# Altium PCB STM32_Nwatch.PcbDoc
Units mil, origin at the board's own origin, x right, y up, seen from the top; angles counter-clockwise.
Board outline 1470.25 x 1330 mil, 2 copper layers (Top Layer, Bottom Layer); 62 components, 59 nets, 208 pads, 89 vias.
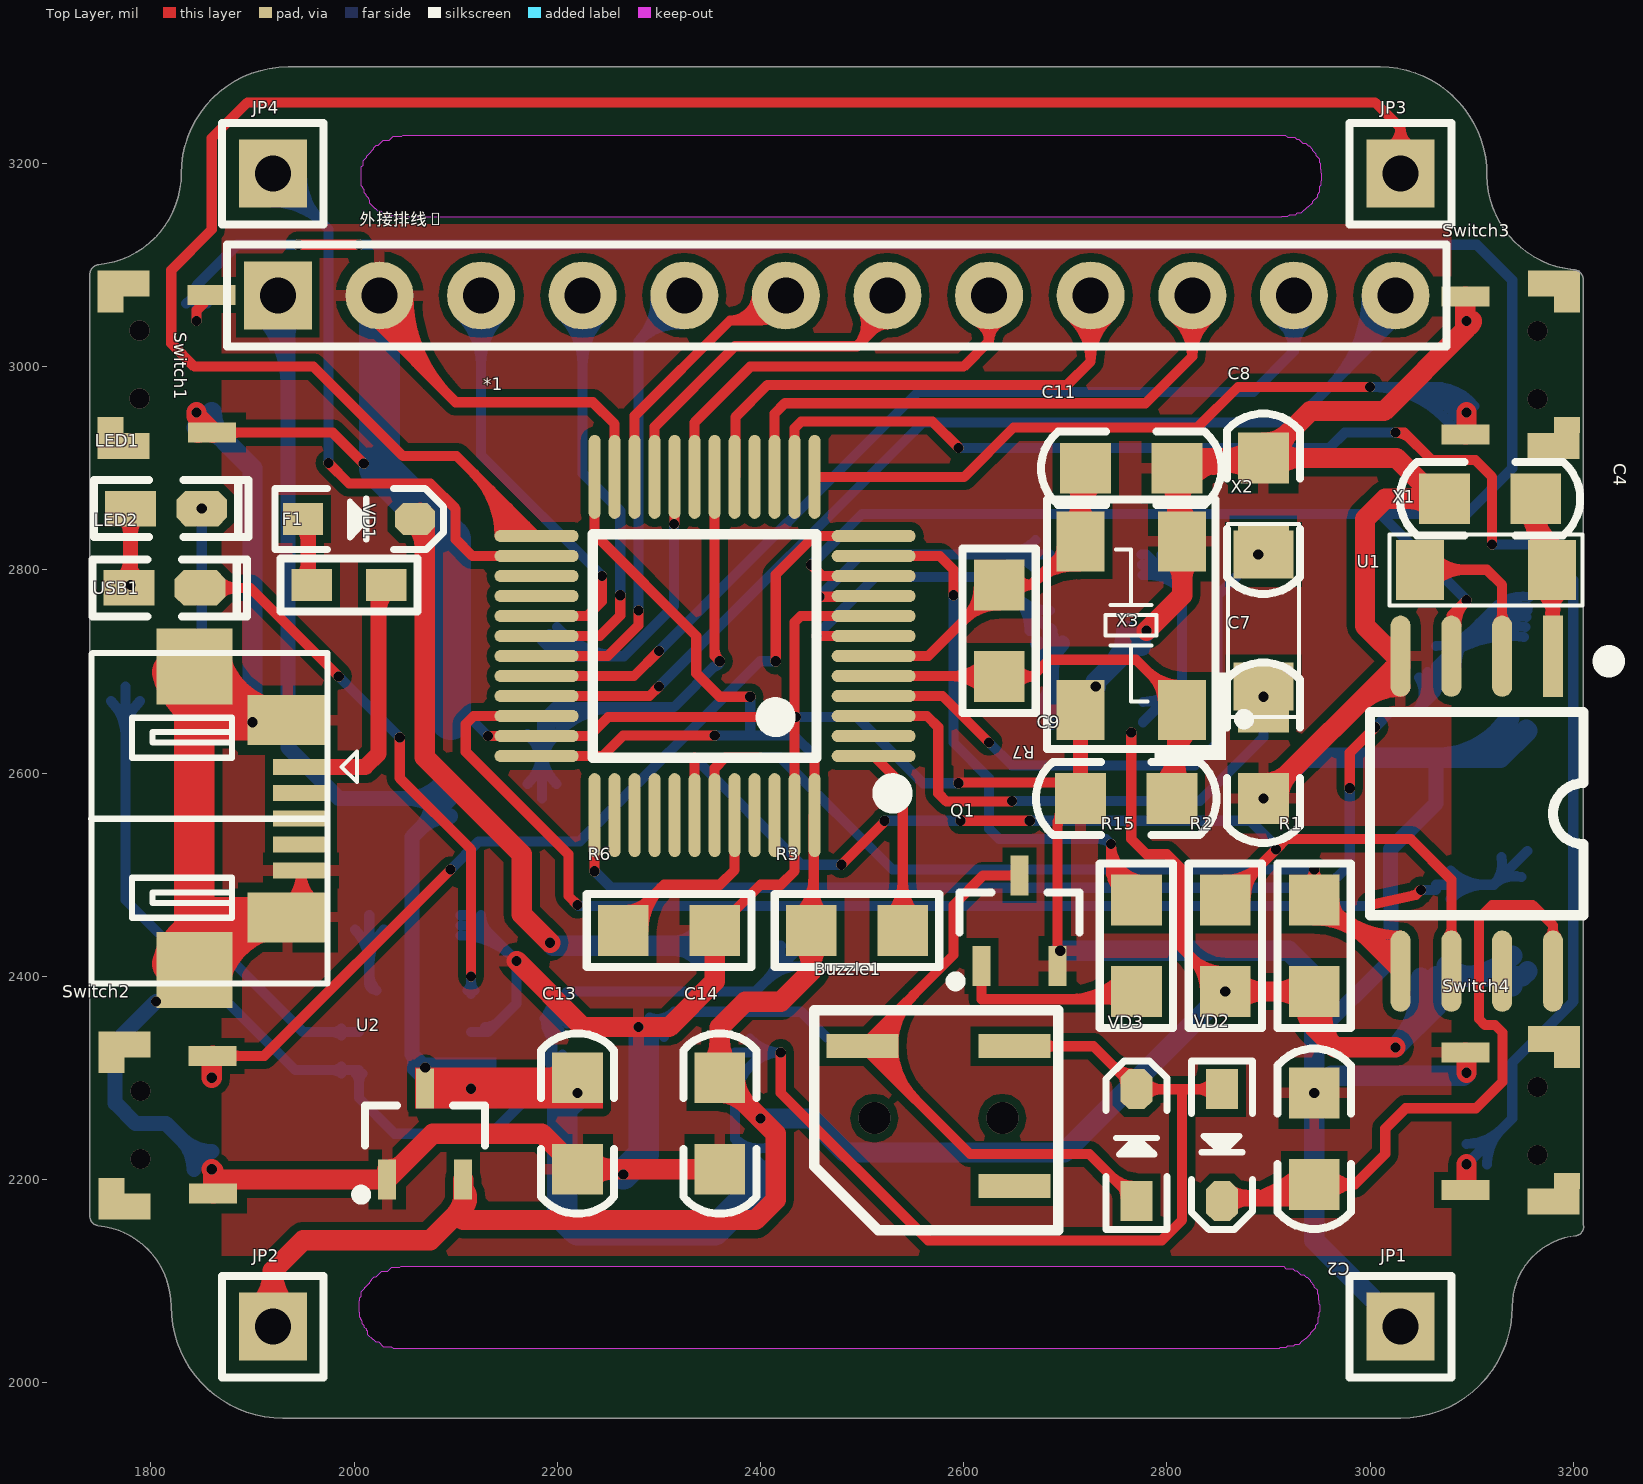
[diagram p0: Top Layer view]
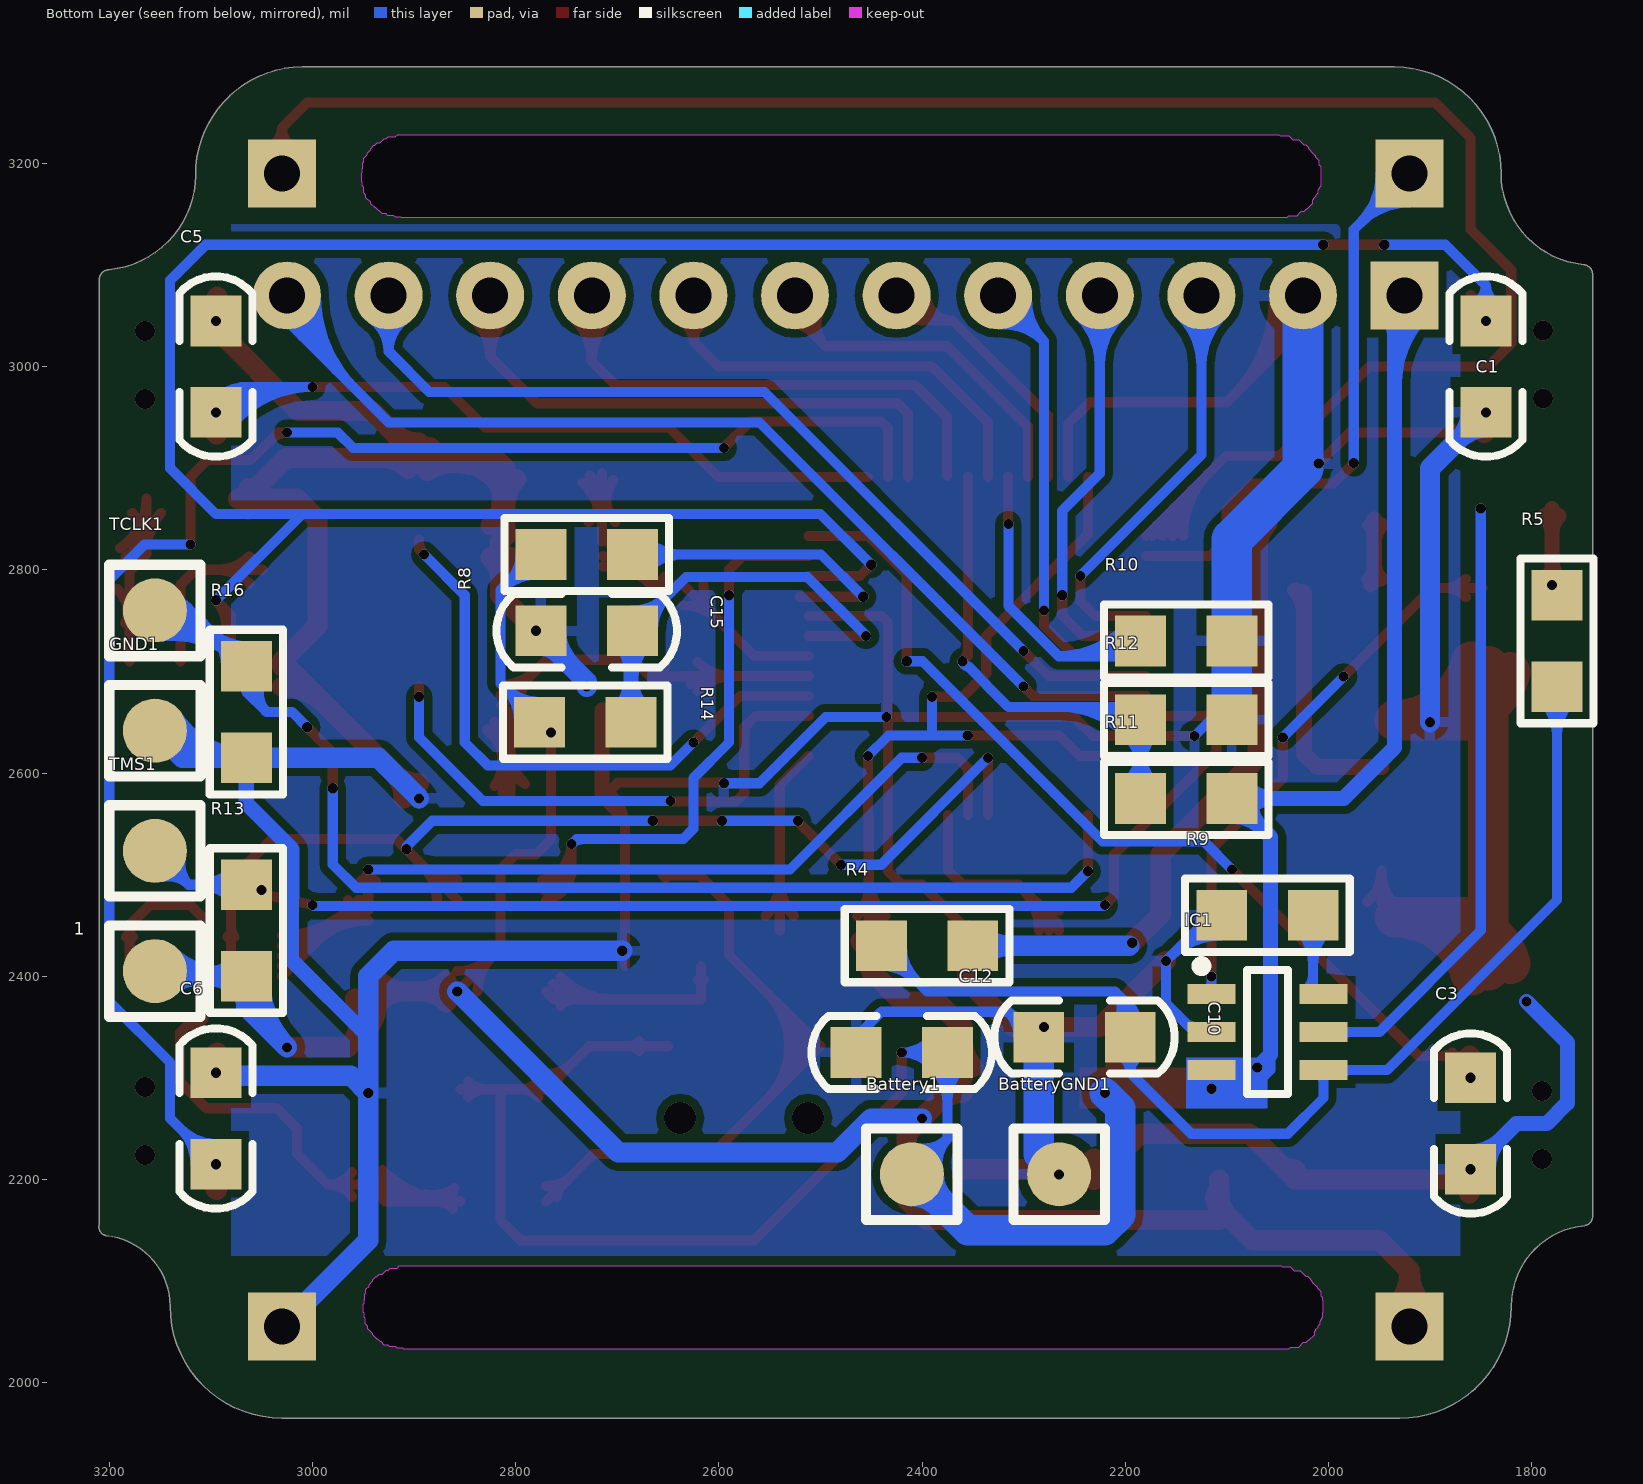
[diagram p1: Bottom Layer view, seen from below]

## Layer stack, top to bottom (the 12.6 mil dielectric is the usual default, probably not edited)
Top Solder: solder mask 0.4, Solder Resist, Dk 3.5
Top Layer: signal copper 1.4
Dielectric 1: dielectric 12.6, FR-4, Dk 4.8
Bottom Layer: signal copper 1.4
Bottom Solder: solder mask 0.4, Solder Resist, Dk 3.5

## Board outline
1820,2075 ccw(c1740,2075) 1747.84,2154.61 cw(c1749.11,2163.73) 1740,2165 1740,3090 cw(c1749.63,3090.81) 1748.82,3100.43 ccw(c1740,3190) 1830,3190 cw(c1935,3190) 1935,3295 3010,3295 cw(c3009.17,3189.17) 3115,3188.35 ccw(c3209.17,3189.17) 3199.94,3095.45 cw(c3199.75,3085.2) 3210,3085 3210,2155 cw(c3201.4,2153.26) 3203.14,2144.66 ccw(c3210,2075) 3140,2075 cw(c3030,2075) 3030,1965 1930,1965 cw(c1930,2075)
cut-out: 2008.86,3202.72 2012.4,3206.26 2012.4,3207.44 2012.8,3207.44 2016.73,3211.38 2017.13,3211.38 2017.13,3212.17 2019.49,3214.53 2019.49,3215.31 2021.85,3217.68 2023.82,3217.68 2028.94,3222.8 2034.84,3222.8 2038.78,3226.73 2047.05,3226.73 2048.23,3227.91 2916.73,3227.91 2919.09,3225.55 2925.79,3225.55 2927.76,3223.58 2929.72,3223.58 2933.66,3219.65 2936.81,3219.65 2939.17,3217.28 2939.96,3217.28 2943.11,3214.13 2943.11,3212.95 2946.65,3209.41 2946.65,3207.83 2949.8,3204.68 2949.8,3201.14 2950.98,3199.96 2950.98,3194.84 2951.38,3194.45 2951.38,3190.91 2952.17,3190.12 2952.17,3183.03 2951.38,3182.24 2951.38,3178.31 2950.2,3177.13 2950.2,3171.61 2947.83,3169.25 2947.83,3166.89 2943.11,3162.17 2943.11,3160.98 2938.78,3156.65 2937.99,3156.65 2935.24,3153.9 2934.84,3153.9 2931.69,3150.75 2927.76,3150.75 2926.18,3149.17 2920.28,3149.17 2918.7,3147.6 2913.19,3147.6 2912.4,3146.81 2040.75,3146.81 2039.17,3148.39 2030.91,3148.39 2028.54,3150.75 2028.54,3151.14 2026.57,3153.11 2023.82,3153.11 2021.46,3155.47 2020.67,3155.47 2015.55,3160.59 2015.55,3163.74 2014.76,3164.53 2014.37,3164.53 2014.37,3165.71 2012.01,3168.07 2012.01,3169.25 2010.04,3171.22 2010.04,3173.98 2008.86,3175.16 2008.86,3175.55 2008.46,3175.94 2008.46,3176.73 2007.28,3177.91 2007.28,3182.24 2006.89,3182.64 2006.89,3194.06 2007.28,3194.45 2007.28,3196.81 2008.86,3198.39
cut-out: 2006.97,2089.37 2010.51,2092.91 2010.51,2094.09 2010.91,2094.09 2014.84,2098.03 2015.24,2098.03 2015.24,2098.82 2017.6,2101.18 2017.6,2101.97 2019.96,2104.33 2021.93,2104.33 2027.05,2109.45 2032.95,2109.45 2036.89,2113.39 2045.16,2113.39 2046.34,2114.57 2914.84,2114.57 2917.2,2112.2 2923.9,2112.2 2925.87,2110.24 2927.83,2110.24 2931.77,2106.3 2934.92,2106.3 2937.28,2103.94 2938.07,2103.94 2941.22,2100.79 2941.22,2099.61 2944.76,2096.06 2944.76,2094.49 2947.91,2091.34 2947.91,2087.8 2949.09,2086.61 2949.09,2081.5 2949.49,2081.1 2949.49,2077.56 2950.28,2076.77 2950.28,2069.69 2949.49,2068.9 2949.49,2064.96 2948.31,2063.78 2948.31,2058.27 2945.94,2055.91 2945.94,2053.54 2941.22,2048.82 2941.22,2047.64 2936.89,2043.31 2936.1,2043.31 2933.35,2040.55 2932.95,2040.55 2929.8,2037.4 2925.87,2037.4 2924.29,2035.83 2918.39,2035.83 2916.81,2034.25 2911.3,2034.25 2910.51,2033.46 2038.86,2033.46 2037.28,2035.04 2029.02,2035.04 2026.65,2037.4 2026.65,2037.8 2024.69,2039.76 2021.93,2039.76 2019.57,2042.13 2018.78,2042.13 2013.66,2047.24 2013.66,2050.39 2012.87,2051.18 2012.48,2051.18 2012.48,2052.36 2010.12,2054.72 2010.12,2055.91 2008.15,2057.87 2008.15,2060.63 2006.97,2061.81 2006.97,2062.2 2006.57,2062.6 2006.57,2063.39 2005.39,2064.57 2005.39,2068.9 2005,2069.29 2005,2080.71 2005.39,2081.1 2005.39,2083.46 2006.97,2085.04 2006.97,2085.83

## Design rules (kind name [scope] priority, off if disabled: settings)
Clearance [All] p1: gap=8
PolygonConnect [All] p1: connectstyle=Relief reliefconductorwidth=10 reliefentries=4 polygonreliefangle="90 Angle" airgapwidth=10
RoutingVias [All] p1: holewidth=28 width=50 viastyle="Through Hole" minholewidth=28 minwidth=50 maxholewidth=28 maxwidth=50
SolderMaskExpansion [All] p1: expansion=4
Width [All] p1: maxlimit=50 minlimit=10 preferedwidth=10
29 further rules are at their usual default settings.

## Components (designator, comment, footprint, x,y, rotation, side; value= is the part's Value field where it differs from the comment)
1 "TEST" "TEST 1.6" 3155,2405 r0 bottom
*1 "STM32F103C8T6" "LQFP48 7x7_M" 2345,2725 r90 top
Battery1 "TEST" "TEST 1.6" 2410,2205 r90 bottom
BatteryGND1 "TEST" "TEST 1.6" 2265,2205 r180 bottom
Buzzle1 "5020 5*5*2MM SMD无源蜂鸣器" "5020 5*5*2MM SMD贴片超薄超小电磁式无源蜂鸣器" 2575,2150 r180 top
C1 "104" "C 0805" 1845,3000 r90 bottom
C2 "104" "C 0805" 2945,2240 r90 top
C3 "104" "C 0805" 1860,2255 r90 bottom
C4 "104" "C 0805" 3118.13,2870 r0 top
C5 "104" "C 0805" 3095,3000 r270 bottom
C6 "104" "C 0805" 3095,2260 r270 bottom
C7 "15pF" "C 0805" 2895,2620 r90 top
C8 "15pF" "C 0805" 2895,2865 r270 top
C9 "22pF" "C 0805" 2760,2575 r0 top
C10 "105" "C 0805" 2240,2340 r180 bottom
C11 "22pF" "C 0805" 2765,2900 r180 top
C12 "105" "C 0805" 2420,2325 r180 bottom
C13 "104" "C 0805" 2220,2255 r90 top
C14 "104" "C 0805" 2360,2255 r90 top
C15 "104" "C 0805" 2730,2740 r180 bottom
F1 "1A" "R 0603" 1995,2785 r0 top
GND1 "TEST" "TEST 1.6" 3155,2641.67 r90 bottom
IC1 "TP4057" SOT23-6N 2060,2345 r270 bottom
JP1 "HDR-1X1" HDR-1X1 3030,2055 r0 top
JP2 "HDR-1X1" HDR-1X1 1920,2055 r0 top
JP3 "HDR-1X1" HDR-1X1 3030,3190 r0 top
JP4 "HDR-1X1" HDR-1X1 1920,3190 r0 top
LED1 "绿色" "LED 0603G" 1815,2860 r0 top
LED2 "红色" "LED 0603R" 1813.5,2781.9 r0 top
Q1 "S9014" SOT23-3L 2655,2455 r0 top
R1 "10K" "R 0805" 2945,2430 r90 top
R2 "10K" "R 0805" 2857.5,2430 r90 top
R3 "0R" "R 0805" 2495,2445 r0 top
R4 "0.8R" "R 0805" 2395,2430 r180 bottom
R5 "100k" "R 0805" 1775,2730 r270 bottom
R6 "10k" "R 0805" 2310,2445 r0 top
R7 "1M" "R 0805" 2635,2740 r270 top
R8 "0" "R 0805" 2730,2815 r180 bottom
R9 "2K" "R 0805" 2060,2460 r180 bottom
R10 "10k" "R 0805" 2140,2730 r0 bottom
R11 "1K" "R 0805" 2140,2575 r180 bottom
R12 "1K" "R 0805" 2140,2652.5 r0 bottom
R13 "10K" "R 0805" 3065,2445 r270 bottom
R14 "10k" "R 0805" 2731.35,2650 r0 bottom
R15 "470R" "R 0805" 2770,2430 r270 top
R16 "10K" "R 0805" 3065,2660 r90 bottom
Switch1 "Switch" 侧按键 1844,3003.86 r90 top
Switch2 "Switch" 侧按键 1845,2255 r90 top
Switch3 "Switch" 侧按键 3110,3000 r270 top
Switch4 "Switch" 侧按键 3110,2256.14 r270 top
TCLK1 "TEST" "TEST 1.6" 3155,2760 r0 bottom
TMS1 "TEST" "TEST 1.6" 3155,2523.33 r0 bottom
U1 "PCF8563T/F4" SOP8W_L 3105,2560 r270 top
U2 "XC6206P332MR" SOT23-3L 2070,2245 r0 top
USB1 "USB-5P" USB-MICRO_A 1855,2555 r270 top
VD1 "1N4148" SOD-323 2005,2850 r0 top
VD2 "1N4148" SOD-323 2854.28,2233.7 r270 top
VD3 "1N4148" SOD-323 2770,2233.7 r90 top
X1 "32.768 KHz" XTAL-3215 3113.96,2800 r0 top
X2 "32.768 KHz" XTAL-3215 2895,2750 r270 top
X3 "8M" XTAL-5032 2765,2745 r90 top
外接排线1 "HDR-1X12" HDR-1X12 1925,3070 r0 top

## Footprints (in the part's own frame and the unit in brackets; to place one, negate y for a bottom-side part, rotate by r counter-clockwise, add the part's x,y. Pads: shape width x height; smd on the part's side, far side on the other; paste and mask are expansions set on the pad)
"5020 5*5*2MM SMD贴片超薄超小电磁式无源蜂鸣器" [mm] "5020 5*5*2MM SMD贴片超薄超小电磁式无源蜂鸣器"
  rect 1.8x0.6 / inner rect 0x0 / far side rect 0x0 all layers, no hole paste+0 mask+0.102: 1(-1.9,-4.6) 2(1.9,-4.6) 3(-1.9,-1.1)
  silkscreen extent -3,-5.5 3.1,0, body extent -2.6,-5.4 2.6,-0.2, height 2
"C 0805" [mil] "无极性贴片电容"
  rect 50x50 smd: 1(-45,0) 2(45,0)
  silkscreen extent -89,-36 89,36, body extent -39,-24 39,24, height 20
HDR-1X1 [mm] "排针，1脚"
  rect 1.7x1.7 hole 0.9: 1(0,0)
  silkscreen extent -1.27,-1.27 1.27,1.27, body extent -1.27,-1.27 1.27,1.27, height 8.5
HDR-1X12 [mm] "排针，13脚"
  rect 1.7x1.7 hole 0.9: 1(0,0)
  round 1.7 hole 0.9: 2(2.54,0) 3(5.08,0) 4(7.62,0) 5(10.16,0) 6(12.7,0) 7(15.24,0) 8(17.78,0) 9(20.32,0) 10(22.86,0) 11(25.4,0) 12(27.94,0)
  silkscreen extent -1.27,-1.27 29.21,1.27, body extent -1.27,-1.27 29.21,1.27, height 8.5
"LED 0603G" [mil] "绿色0603LED"
  rect 50x35 smd: 1(-35,0.26)
  oct 50x35 smd: 2(35,0.26)
  silkscreen extent -71,-28 81,28, body extent -31,-16 32,16, height 24
"LED 0603R" [mil] "红色0603LED"
  rect 50x35 smd: 1(-35,0.26)
  oct 50x35 smd: 2(35,0.26)
  silkscreen extent -71,-28 81,28, body extent -31,-16 32,16, height 24
"LQFP48 7x7_M" [mm] "48脚，体宽7x7mm，脚距0.5mm"
  oval 0.3x2.1 smd: 1(-2.75,-4.227) 2(-2.25,-4.227) 3(-1.75,-4.227) 4(-1.25,-4.227) 5(-0.75,-4.227) 6(-0.25,-4.227) 7(0.25,-4.227) 8(0.75,-4.227) 9(1.25,-4.227) 10(1.75,-4.227) 11(2.25,-4.227) 12(2.75,-4.227) 25(2.75,4.202) 26(2.25,4.202) 27(1.75,4.202) 28(1.25,4.202) 29(0.75,4.202) 30(0.25,4.202) 31(-0.25,4.202) 32(-0.75,4.202) 33(-1.25,4.202) 34(-1.75,4.202) 35(-2.25,4.202) 36(-2.75,4.202)
  oval 2.1x0.3 smd: 13(4.227,-2.75) 14(4.227,-2.25) 15(4.227,-1.75) 16(4.227,-1.25) 17(4.227,-0.75) 18(4.227,-0.25) 19(4.227,0.25) 20(4.227,0.75) 21(4.227,1.25) 22(4.227,1.75) 23(4.227,2.25) 24(4.227,2.75) 37(-4.227,2.75) 38(-4.227,2.25) 39(-4.227,1.75) 40(-4.227,1.25) 41(-4.227,0.75) 42(-4.227,0.25) 43(-4.227,-0.25) 44(-4.227,-0.75) 45(-4.227,-1.25) 46(-4.227,-1.75) 47(-4.227,-2.25) 48(-4.227,-2.75)
  silkscreen extent -3.93,-4.95 2.79,2.79, body extent -4.5,-4.5 4.5,4.5, height 1.45
"R 0603" [mil] "1/10W贴片电阻"
  rect 40x31.5 smd: 1(-36.5,0) 2(36.5,0)
  silkscreen extent -68,-26 68,26, body extent -31,-16 32,16, height 16
"R 0805" [mil] "1/8W贴片电阻"
  rect 50x50 smd: 1(-45,0) 2(45,0)
  silkscreen extent -81,-36 81,36, body extent -39,-25 39,25, height 20
SOD-323 [mm] "1.8x1.3X0.9mm（长宽高，不包括引脚）"
  rect 1x0.8 smd: 1(-1.4,0)
  oct 1x0.8 smd: 2(1.4,0)
  silkscreen extent -2.11,-0.76 2.11,0.76, body extent -1.34,-0.63 1.31,0.67, height 1
SOP8W_L [mil] "5.3*8.3*1.8mm（长宽高）"
  rect 80x19.68 smd: 1(-155,75)
  oval 80x19.68 smd: 2(-155,25) 3(-155,-25) 4(-155,-75) 5(155,-75) 6(155,-25) 7(155,25) 8(155,75)
  silkscreen extent -156,-105 100,136, body extent -155,-104 155,104, height 75
SOT23-3L [mm] "3x1.3x1mm(长宽高)"
  rect 0.45x1 smd: 1(-0.95,-1.143) 2(0.95,-1.143) 3(0,1.125)
  silkscreen extent -1.72,-1.65 1.5,0.7, body extent -1.5,-1.2 1.5,1.2, height 1.05
SOT23-6N [mm] "3x1.6x1.1mm(长宽高)"
  rect 0.5x1.2 smd: 1(-0.95,-1.4) 2(0,-1.4) 3(0.95,-1.4) 4(0.95,1.4) 5(0,1.4) 6(-0.95,1.4)
  silkscreen extent -1.78,-1.78 1.55,0.51, body extent -1.5,-1.4 1.5,1.4, height 1.15
"TEST 1.6" [mm] "测试点1.6mm"
  round 1.6 smd: 1(0,0)
  silkscreen extent -1.14,-1.14 1.14,1.14
USB-MICRO_A [mm] "micro型USB ，5.9*8.2*2.5mm"
  rect 0.4x1.4 smd: 1(-1.296,2.355) 2(-0.648,2.355) 3(0,2.355) 4(0.648,2.355) 5(1.295,2.355)
  rect 1.9x1.9 smd: 5(-3.81,-0.312) 5(3.784,-0.312)
  rect 1.25x2 smd: 5(-2.464,2.025) 5(2.464,2.025)
  silkscreen extent -4.14,-2.89 4.11,3.75, body extent -3.98,-2.77 3.98,2.65, height 2.69
XTAL-3215 [mm]
  rect 1.2x1.5 smd: 1(-1.65,0) 2(1.65,0)
  silkscreen extent -2.41,-0.89 2.41,0.89, body extent -1.6,-0.75 1.6,0.75, height 0.81
XTAL-5032 [mm]
  rect 1.5x1.2 smd: 1(-2.108,-1.27) 2(2.108,-1.27) 3(2.108,1.27) 4(-2.108,1.27)
  silkscreen extent -3.35,-2.95 3.15,2.11, body extent -2.5,-1.6 2.5,1.6, height 1
侧按键 [mm] "侧边按键的轻触开关2*4*3.5mm"
  rect 0.5x1.2 smd: 1(-1.749,-0.413) 2(1.691,-0.403)
  rect 0.65x1.3 smd: ""(-2.079,1.807) ""(1.981,1.797)
  rect 0.4x0.65 smd: ""(-1.559,2.127) ""(1.461,2.127)
  body extent -2.35,-0.81 2.3,3.49, height 1.9

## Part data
1 Battery1 BatteryGND1 GND1 TCLK1 TMS1: "测试点"
Buzzle1: library part "5020 SMD无源蜂鸣器", "5020 5*5*2MM SMD贴片超薄超小电磁式无源蜂鸣器"
C1 C2 C3 C4 C5 C6 C10 C12: library part C, "无极性贴片电容"
C7 C8 C9 C11 C13 C14 C15: library part "Cap  贴片"
F1: library part FUSE
IC1: library part TP4057/4059, "500mA/600mA锂电池充电管理IC"
JP1 JP2 JP3 JP4: library part "Header 1", "1P接插件"
LED1 LED2: library part LED-SMD, "贴片LED"
Q1: library part 9014-SMD, "低噪放大-NPN型"
R1 R2 R4 R5 R9 R11 R12 R13 R15 R16: library part R, "贴片电阻"
R3 R6 R7 R8 R10 R14: library part "Res  贴片"
Switch1 Switch2 Switch3 Switch4: library part 2X4X3.5侧按键, "测贴 轻触开关 2*4*3.5MM"
U1: library part PCF8563T, "时钟芯片"
U2: library part AMS1117
USB1: "微型USB母座"
VD1 VD2 VD3: "高速开关二极管"
X1 X2: library part XTAL, "Crystal Oscillator"
X3: library part XTAL-4, "4脚晶振"
外接排线1: library part "Header 12", "12P接插件"

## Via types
v1: diameter 10, hole 10, Top Layer to Bottom Layer, 79 vias
v2: diameter 19.68, hole 19.68, Top Layer to Bottom Layer, 8 vias
v3: diameter 31.5, hole 31.5, Top Layer to Bottom Layer, 2 vias

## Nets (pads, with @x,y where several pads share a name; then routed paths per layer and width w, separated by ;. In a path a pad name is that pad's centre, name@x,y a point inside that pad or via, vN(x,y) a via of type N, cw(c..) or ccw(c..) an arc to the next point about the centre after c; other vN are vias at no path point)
3V3: 1.1 *1.24 *1.36 *1.48 C14.2 JP2.1 R1.1 R2.1 R3.1 R8.1 R13.2 R14.2 U2.2 | length 4444.4
  Top Layer w10: *1.36 2244.73,2616.73 2265,2637 v1(2355,2637) ; *1.24 2236.73,2835 2336.84,2734.89 2336.84,2698.16 2360,2675 v1(2390,2675) ; R3.1@2435.86,2459.14 ccw(c2395.71,2499.29) 2452.49,2499.29 ; R3.1@2442.93,2452.07 ccw(c2419.85,2475.15) 2452.49,2475.15 ; R3.1 2452.49,2447.49 2452.49,2557.8 *1.48 v1(2453.27,2616.73) ; 2452.49,2487.28 ccw(c2492.28,2487.28) R3.1@2464.14,2459.14 ; v1(2765,2640) 2765,2535 2780,2520 2800,2520 2815,2505 2815,2427.5 v1(2857.5,2385) ; R2.1@2837.5,2385 ccw(c2789.22,2385) 2823.36,2419.14 ccw(c2857.5,2453.28) R2.1@2857.5,2405
  Top Layer w20: JP2.1@1903.76,2071.94 ccw(c1867.28,2110) 1920,2110 ; JP2.1 1920,2110 ; JP2.1@1936.24,2071.94 cw(c1972.72,2110) 1920,2110 ; 2097.49,2162.49 ccw(c2070.81,2189.17) U2.2@2108.54,2189.17 ; U2.2@2108.29,2189.9 cw(c2098.17,2181.64) 2107.4,2172.4 ; C14.2@2349.39,2310.61 ccw(c2323.79,2336.21) 2360,2336.21 ccw(c2396.21,2336.21) C14.2@2370.61,2310.61 ; C14.2@2360,2285 cw(c2360,2248.79) 2385.61,2274.39 cw(c2411.21,2300) C14.2@2375,2300 ; R3.1@2439.39,2434.39 cw(c2413.79,2408.79) 2450,2408.79 cw(c2486.21,2408.79) R3.1@2460.61,2434.39 ; R3.1 2450,2405 2420,2375 2385,2375 2360,2350 C14.2 v1(2400,2260) 2415,2245 2415,2180 2395,2160 2107.4,2160 U2.2 2107.4,2172.4 ; v1(2857.5,2385) R1.1 2945,2350 ; R2.1@2868.11,2374.39 cw(c2893.71,2348.79) 2893.71,2385 cw(c2893.71,2421.21) R2.1@2868.11,2395.61 ; R1.1@2934.39,2374.39 ccw(c2908.79,2348.79) 2908.79,2385 ccw(c2908.79,2421.21) R1.1@2934.39,2395.61 ; R1.1@2934.66,2374.14 cw(c2911.67,2350) 2945,2350 ; R1.1@2940.61,2387.4 ccw(c2969.08,2371.82) 2946.13,2348.87 ; R1.1@2955.34,2374.14 ccw(c2978.33,2350) 2945,2350 ; R1.1@2958.16,2377.8 ccw(c2993.46,2358.46) 2965,2330 ; v1(3025,2330) 2965,2330 ; 1920,2110 1950,2140 2075,2140 2107.4,2172.4 ; 2945,2350 2965,2330
  Bottom Layer w10: v1(2355,2637) 2433,2637 v1(2453.27,2616.73) ; 2390,2637 v1(2390,2675) ; R8.1 2780,2815 2815,2780 ; R8.1@2775.5,2805.01 cw(c2777.06,2773.93) R8.1@2799.07,2795.93 ; R8.1@2776,2795.03 cw(c2778.57,2743.58) 2815,2780 ; R14.2 2815,2688.65 2815,2780 ; R14.2@2776.35,2670 ccw(c2776.35,2718.28) 2810.5,2684.14 ccw(c2844.64,2650) R14.2@2796.35,2650 ; R8.1@2795,2815 ccw(c2831.21,2815) 2805.61,2789.39
  Bottom Layer w20: v1(2400,2260) 2450,2260 2483.51,2226.49 2698.99,2226.49 v1(2857.5,2385) ; R13.2@3050.06,2398.71 cw(c2963.74,2391.26) v1(3025,2330) 3065,2370 ; 3055.38,2360.38 ccw(c3019.67,2396.09) R13.2@3069.98,2400.43 ; R13.2@3056,2388 cw(c3042.5,2370) 3065,2370 ; R13.2@3074,2388 ccw(c3087.5,2370) 3065,2370 ; R13.2@3075.61,2389.39 cw(c3101.21,2363.79) 3101.21,2400 cw(c3101.21,2436.21) R13.2@3075.61,2410.61 ; 3091.03,2400 ccw(c3091.03,2468.97) 1.1@3139.8,2420.2 ; 3115.18,2400 cw(c3115.18,2365.18) 1.1@3139.8,2389.8 ; 1.1 3150,2400 R13.2 3065,2370
+: Battery1.1 Buzzle1.1 C12.2 C13.2 IC1.3 R11.2 U2.3 VD2.1 VD3.2 外接排线1.1 | length 3309.4
  Top Layer w10: v1(2420,2325) 2420,2285 2565,2140 2795,2140 2815,2160 2815,2288.82 ; Buzzle1.1 2727.72,2331.1 VD3.2 2815,2288.82 ; Buzzle1.1@2678.24,2326.29 cw(c2689.87,2314.66) 2689.87,2331.1 cw(c2689.87,2347.55) Buzzle1.1@2678.24,2335.92 ; 2744.93,2313.89 ccw(c2770,2338.96) VD3.2@2770,2303.5 ; 2754.44,2304.38 cw(c2742.81,2292.76) VD3.2@2759.25,2292.76 ; VD3.2@2777.6,2281.22 cw(c2795.95,2262.87) 2795.95,2288.82 cw(c2795.95,2314.77) VD3.2@2777.6,2296.42 ; VD2.1@2846.68,2281.22 ccw(c2828.33,2262.87) 2828.33,2288.82 ccw(c2828.33,2314.77) VD2.1@2846.68,2296.42 ; VD2.1 2815,2288.82
  Top Layer w20: v1(2115,2289.29) 2209.29,2289.29 C13.2 ccw(c2232.61,2287.39) C13.2@2215.09,2284.07 ; 2157.93,2289.29 ccw(c2157.93,2362.07) C13.2@2209.39,2310.61
  Bottom Layer w10: 2057,2323 2057,2308 2075.71,2289.29 v1(2115,2289.29) 2115.12,2289.41 IC1.3 ; IC1.3@2111.69,2304.17 cw(c2103.43,2295.91) 2115.12,2295.91 cw(c2126.81,2295.91) IC1.3@2118.54,2304.17 ; C12.2@2360.86,2310.86 cw(c2326.72,2276.72) 2375,2276.72 cw(c2423.28,2276.72) C12.2@2389.14,2310.86 ; Battery1.1@2384.02,2210.2 ccw(c2351.68,2216.68) 2375,2240 ; C12.2@2389.85,2311.6 cw(c2420,2284.38) v1(2420,2325) ; C12.2@2389.85,2338.4 ccw(c2420,2365.62) v1(2420,2325) ; Battery1.1@2404.8,2230.98 cw(c2398.32,2263.32) 2375,2240 ; Battery1.1 2375,2240 ; 2375,2240 C12.2 v1(2420,2325)
  Bottom Layer w15: 外接排线1.1@1906.64,3051.64 cw(c1838.17,2983.17) 1935,2983.17 ; 外接排线1.1@1917.25,3062.25 cw(c1874.39,3019.39) 1935,3019.39 ; 外接排线1.1 1935,3060 1935,2625 1985,2575 R11.2 2057,2537 2057,2323 v1(2070,2310) ; 1935,3031.46 cw(c1963.54,3031.46) 外接排线1.1@1943.36,3051.64 ; R11.2@2077.5,2575 cw(c2035.25,2575) 2065.13,2545.13 cw(c2095,2515.25) R11.2@2095,2557.5 ; R11.2@2082.63,2562.63 ccw(c2052.75,2532.75) 2052.75,2575 ccw(c2052.75,2617.25) R11.2@2082.63,2587.37
  Bottom Layer w30: v1(2220,2285) 2205,2270 2205,2165 2220,2150 2355,2150 Battery1.1 ; Battery1.1@2393.5,2205 cw(c2353.68,2205) 2381.84,2176.84 cw(c2410,2148.68) Battery1.1@2410,2188.5
ADC: *1.18 R11.1 R12.2 | length 784.2
  Top Layer w10: 2354.84,2722.45 ccw(c2372.45,2722.45) v1(2360,2710) 2354.84,2715.16 *1.18
  Bottom Layer w10: R11.1@2170.86,2589.14 ccw(c2136.72,2623.28) 2185,2623.28 ccw(c2233.28,2623.28) R11.1@2199.14,2589.14 ; R12.2@2170.86,2638.36 cw(c2136.72,2604.22) 2185,2604.22 cw(c2233.28,2604.22) 2199.14,2638.36 cw(c2263.46,2574.04) 2263.46,2665 ; R11.1 R12.2 ; R12.2@2192.07,2645.43 cw(c2239.32,2598.18) 2239.32,2665 ; 2215.18,2665 ccw(c2215.18,2622.32) R12.2 ; 2355,2705 2354.54,2705 ; v1(2360,2710) cw(c2354.54,2710.48) 2354.54,2705 ; R12.2 2197.5,2665 2315,2665 2337,2687 2337,2687.46 2354.54,2705
BOOT0: *1.44 R6.1 | length 295.5
  Top Layer w10: R6.1 2265,2450 2305,2490 2360,2490 2374.53,2504.53 *1.44 ; R6.1@2265,2465 ccw(c2265,2501.21) 2290.61,2475.61 ; R6.1@2275,2445 cw(c2311.21,2445) 2285.61,2470.61 ; R6.1@2285,2445 cw(c2345.36,2445) 2302.68,2487.68
BUZZLE: *1.11 R15.1 | length 697.1
  Top Layer w10: *1.11 2576.42,2813.58 2590,2800 v1(2590,2775) ; 2745,2505.55 ccw(c2776.17,2505.55) R15.1 2745,2500 v1(2745,2530) ccw(c2781.11,2530) R15.1@2773.96,2494.6 ; 2745,2517.78 ccw(c2778.64,2517.78) R15.1@2771.98,2484.8
  Bottom Layer w10: v1(2590,2775) 2590,2630 2625,2595 2625,2545 2635,2535 2740,2535 v1(2745,2530) ccw(c2732.93,2517.93) 2732.93,2535
D+: USB1.3
D-: USB1.2
GND: *1.8 *1.23 *1.35 *1.47 BatteryGND1.1 C1.1 C2.2 C3.1 C4.1 C5.1 C6.1 C7.1 C8.1 C9.1 C10.1 C11.1 C12.1 C13.1 C14.1 C15.1 GND1.1 IC1.2 JP1.1 Q1.2 R6.2 R9.1 R10.1 R12.1 R16.1 Switch1.1 Switch2.1 Switch3.1 Switch4.1 U1.4 U2.1 USB1.5 X3.2 X3.4 外接排线1.2 | length 9928.6
  Top Layer w10: Switch1.1 1861.26,2935 1979.09,2935 v1(2009.54,2904.54) ; Switch1.1@1877.46,2931.58 cw(c1885.73,2923.31) 1885.73,2935 cw(c1885.73,2946.69) Switch1.1@1877.46,2938.42 ; USB1.5@1934.72,2458.01 1947.72,2471.01 1947.72,2504.01 ccw(c1988.3,2504) USB1.5@1962.13,2472.99 ; USB1.5@1935.62,2471.87 ccw(c1906.41,2501.08) USB1.5@1947.72,2501.08 ; 外接排线1.2@2023.46,3070 ccw(c2092.18,3070) 2043.59,3021.41 ; 外接排线1.2 2025,3040 2100,2965 2235,2965 2256.42,2943.58 *1.23 ; 外接排线1.2@2033.46,3070 ccw(c2126.33,3070) 2060.66,3004.34 ; 外接排线1.2@2043.46,3070 ccw(c2160.47,3070) 2077.73,2987.27 ; 外接排线1.2@2053.46,3070 ccw(c2194.61,3070) 2094.81,2970.19 ; v1(2131.87,2636.42) *1.35 2231.42,2636.42 2250,2655 2428.58,2655 ; R6.2 2400,2490 2420,2490 2433.58,2503.58 *1.47 2433.58,2748.58 2439.53,2754.53 *1.8 ; v1(2595,2590) 2595.5,2590.5 2699.5,2590.5 C9.1 2692.4,2552.4 Q1.2 ; 2692.4,2544.58 cw(c2745.42,2544.58) C9.1@2707.93,2582.07
  Top Layer w15: C9.1 X3.4
  Top Layer w20: v1(1845,2955) v1@1845,2951.26 ; Switch1.1@1846.61,2934.91 ccw(c1835.85,2942.1) v1@1845,2951.26 ; v1(1860,2210) 1861.26,2208.74 Switch2.1 ; Switch1.1@1861.26,2935 v1@1845,2951.26 ; 1870,2200 U2.1 2077.6,2245 2185,2245 C13.1 C14.1 ; U2.1@2032.6,2209.68 ccw(c2032.6,2233.07) 2049.13,2216.53 ; v1(2160,2415) 2225,2350 v1@2275,2350 ; C13.1@2230.61,2199.39 cw(c2256.21,2173.79) 2256.21,2210 cw(c2256.21,2246.21) C13.1@2230.61,2220.61 ; v1(2280,2350) v1@2275,2350 ; R6.2 2355,2395 2310,2350 v1@2275,2350 ; v1(2780,2740) 2815,2775 X3.2 ; C11.1@2799.39,2889.39 cw(c2773.79,2863.79) 2810,2863.79 cw(c2846.21,2863.79) 2820.61,2889.39 cw(c2870.36,2839.64) C8.1@2870.36,2910 ; X3.2@2805.37,2812.46 cw(c2782.11,2789.21) 2815,2789.21 cw(c2847.89,2789.21) X3.2@2824.63,2812.46 ; X3.2@2810,2833 C11.1 2820,2910 C8.1 ; C11.1@2810,2878.86 ccw(c2859.96,2878.86) X3.2@2824.63,2843.54 ; 2814.24,2863.04 cw(c2841.59,2870.37) C11.1@2820.94,2889.74 ; 2845.85,2903.43 cw(c2859.37,2852.97) C8.1@2887.05,2897.28 ; C8.1@2884.39,2899.39 ccw(c2858.79,2873.79) 2858.79,2910 ccw(c2858.79,2946.21) C8.1@2884.39,2920.61 ; v1(2895,2575) 3030,2710 2995,2744.99 2995,2850 3015,2870 C4.1@3066.06,2870 ; C7.1@2895,2590 ccw(c2895,2626.21) 2920.61,2600.61 ccw(c2946.21,2575) C7.1@2910,2575 ; C8.1@2895,2925 ccw(c2895,2961.21) 2920.61,2935.61 ccw(c2946.21,2910) C8.1@2910,2910 ; C8.1@2905.61,2899.39 cw(c2931.21,2873.79) 2931.21,2910 cw(c2931.21,2946.21) C8.1@2905.61,2920.61 ; 2987.33,2667.33 cw(c3030,2624.67) U1.4@3030,2685 ; U1.4@3021.47,2701.47 cw(c3030,2692.95) U1.4@3030,2705 ; C4.1@3062.52,2859.39 ccw(c3036.91,2833.79) 3036.91,2870 ccw(c3036.91,2906.21) C4.1@3062.52,2880.61 ; C4.1 C4.1@3066.06,2870 ; Switch4.1 3095,2323.74 v1(3095,2305) ; Switch3.1 3093.74,3036.27 3013.74,2956.26 2941.26,2956.26 C8.1 ; C8.1 3026.06,2910 C4.1@3066.06,2870 ; 3098.25,3040.78 ccw(c3094.03,3045) 3100,3045 cw(c3094.03,3045) 3098.25,3040.78
  Top Layer w40: USB1.5@1820.91,2699.1 ccw(c1882.45,2715.76) 1882.45,2652.01 ; USB1.5@1820.99,2412.21 cw(c1881.7,2394.88) 1881.7,2458.01 ; USB1.5@1842.72,2406.01 1842.72,2457.72 ; USB1.5@1842.72,2705.01 1842.72,2662.28 ; USB1.5@1859.45,2401.23 cw(c1934.72,2379.73) 1934.72,2458.01 1843.01,2458.01 1842.72,2457.72 ; USB1.5@1859.52,2709.55 ccw(c1934.72,2729.91) 1934.72,2652.01 1852.99,2652.01 1842.72,2662.28 ; USB1.5@1830.42,2418.31 ccw(c1800.71,2448.02) 1842.72,2448.02 ; USB1.5@1830.42,2418.31 ccw(c1800.71,2448.02) 1842.72,2448.02 ; USB1.5@1830.42,2418.31 ccw(c1800.71,2448.02) 1842.72,2448.02 ; USB1.5@1830.42,2692.7 cw(c1800.71,2663) 1842.72,2663 ; USB1.5@1830.42,2692.7 cw(c1800.71,2663) 1842.72,2663 ; USB1.5@1830.42,2692.7 cw(c1800.71,2663) 1842.72,2663 ; 1842.72,2448.02 ccw(c1884.73,2448.02) USB1.5@1855.03,2418.31 ; 1842.72,2448.02 ccw(c1884.73,2448.02) USB1.5@1855.03,2418.31 ; 1842.72,2448.02 ccw(c1884.73,2448.02) USB1.5@1855.03,2418.31 ; 1842.72,2457.72 1842.72,2662.28 ; 1842.72,2663 cw(c1884.73,2663) USB1.5@1855.03,2692.7 ; 1842.72,2663 cw(c1884.73,2663) USB1.5@1855.03,2692.7 ; 1842.72,2663 cw(c1884.73,2663) USB1.5@1855.03,2692.7
  Bottom Layer w10: R12.1@2095,2673.29 v1(2131.87,2636.42) ; R9.1@2105,2440 cw(c2105,2367.57) 2156.21,2418.79 ; R9.1@2105,2450 cw(c2105,2401.72) 2139.14,2435.86 ; R9.1 2115,2460 v1(2160,2415) 2160,2373.38 2131.62,2345 IC1.2 ; R9.1@2125,2460 ccw(c2149.14,2460) 2132.07,2442.93 ; IC1.2@2128.9,2349.84 ccw(c2128.9,2368.09) 2141.8,2355.19 ; C10.1 2290,2340 2315,2365 ; C10.1@2290.97,2359.09 ccw(c2298.1,2381.9) 2315,2365 ; C10.1@2305,2340.31 cw(c2339.15,2340.84) 2315,2365 ; v1(2435,2655) 2495,2655 2560,2590 v1(2595,2590) ; C12.1@2465,2340 2440,2365 2315,2365
  Bottom Layer w15: v1(1805,2375) 1764.66,2334.66 1764.66,2276.09 1765,2275.75 1765,2275 1785,2255 1815,2255 v1(1860,2210) ; C3.1@1842.5,2210 ccw(c1800.25,2210) 1830.13,2239.87 ccw(c1860,2269.75) C3.1@1860,2227.5 ; 2945,2340.5 3020.5,2416 3020.5,2478.49 3020,2478.99 3020,2525 3065,2570 R16.1
  Bottom Layer w20: C1.1@1845,2940 cw(c1845,2903.79) 1870.61,2929.39 cw(c1896.21,2955) C1.1@1860,2955 ; v1(1845,2955) 1900,2900 v1(1900,2650) ; v1(2695,2425) 2920,2425 2945,2400 2945,2340.5 v1(2945,2285) ; v1(2730,2685) 2730,2690 v1(2780,2740) ; 2745.86,2705.86 ccw(c2711.72,2740) C15.1@2760,2740 ; C15.1@2757.93,2717.93 cw(c2775,2700.86) C15.1@2775,2725 ; v1(2895,2575) 2935,2615 R16.1 ; JP1.1 2945,2140 v1(2945,2285) ; v1(3095,2305) 3092,2302 2962,2302 v1(2945,2285) ; 3102.38,2615 ccw(c3102.38,2676.75) GND1.1@3153.76,2642.5 ; GND1.1@3137.11,2653.59 cw(c3065,2701.67) R16.1 ; GND1.1 3128.33,2615 R16.1
  Bottom Layer w30: v1(2265,2205) 2285,2225 C10.1
  Bottom Layer w40: 外接排线1.2 2025,2900 2095,2830 R10.1 2095,2673.29 R12.1
  other v1: 3095,3045
IIC_SCL: *1.21 外接排线1.7 | length 433.4
  Top Layer w10: *1.21 2295.79,2940.79 2375,3020 2495,3020 ; 外接排线1.7@2500.1,3056.21 cw(c2473.51,3041.49) 2495,3020 ; 2504.39,3029.39 ccw(c2485.6,3048.18) 外接排线1.7@2508.85,3061.06 ; 2510.55,3035.55 cw(c2525,3021.1) 外接排线1.7@2525,3041.54 ; 外接排线1.7 2525,3050 2495,3020
IIC_SDA: *1.22 外接排线1.6 | length 436.7
  Top Layer w10: *1.22 2276.1,2951.56 2370,3045.46 ; 2380.38,3045.46 ccw(c2380.38,3071.64) 外接排线1.6@2406.55,3070.68 ; 2390.75,3045.46 ccw(c2390.75,3071.26) 外接排线1.6@2416.54,3070.31 ; 外接排线1.6@2396.55,3071.05 cw(c2370,3072.03) 2370,3045.46 ; 2401.13,3045.46 ccw(c2401.13,3070.88) 外接排线1.6@2426.53,3069.94 ; 外接排线1.6@2401.32,3054.2 cw(c2395.56,3050.36) 2400.46,3045.46 ; 外接排线1.6@2409.2,3046.32 ccw(c2405.36,3040.56) 2400.46,3045.46 ; 外接排线1.6 2400.46,3045.46 ; 2370,3045.46 2400.46,3045.46
MPU_INT: *1.19 外接排线1.8 | length 469.8
  Top Layer w10: *1.19 2335.16,2945.16 2390,3000 2600,3000 2625,3025 ; 外接排线1.8@2612.8,3044.28 cw(c2603.66,3025) 2625,3025 ; 外接排线1.8 2625,3025 ; 外接排线1.8@2637.2,3044.28 ccw(c2646.34,3025) 2625,3025
Net*1_5: *1.5 C9.2 R7.2 X3.1 | length 915.3
  Top Layer w10: *1.5 R7.2@2634.53,2695.47 ; 2585.57,2695.47 cw(c2585.57,2645.57) R7.2@2620.86,2680.86 ; 2587.86,2695.47 ccw(c2587.86,2742.14) R7.2@2620.86,2709.14 ; 2609.72,2695.47 cw(c2609.72,2669.72) R7.2@2627.93,2687.93 ; R7.2 2667.78,2695 2684.3,2711.53 2769.61,2711.53 2814.14,2667 2805,2657.86 C9.2 ; R7.2@2652.79,2685.85 cw(c2667.77,2678.15) 2667.77,2695 cw(c2667.77,2711.85) R7.2@2652.79,2704.15 ; 2780.19,2700.94 ccw(c2815,2735.75) X3.1@2815,2686.53 ; 2784.46,2696.68 cw(c2755.69,2667.91) X3.1@2796.38,2667.91 ; C9.2@2790.86,2589.14 ccw(c2756.72,2623.28) 2805,2623.28 ccw(c2853.28,2623.28) C9.2@2819.14,2589.14 ; C9.2@2795,2592.32 ccw(c2776.16,2624.96) 2812.56,2615.2 ; X3.1@2797.26,2683.87 ccw(c2815,2701.61) X3.1@2815,2676.53 ; C9.2@2805,2586.99 cw(c2884.1,2586.99) X3.1@2828.17,2642.93 ; 2805,2611.14 cw(c2859.96,2611.14) X3.1@2821.1,2650 ; 2808.92,2601.64 ccw(c2831.95,2595.47) C9.2@2812.96,2581.05 ; 2814.2,2621.35 ccw(c2852.52,2611.08) C9.2@2820.93,2587.09
Net*1_6: *1.6 C11.2 R7.1 X3.3 | length 772.7
  Top Layer w10: *1.6 2565.16,2715.16 R7.1 2666.14,2785 ; R7.1@2615,2785 cw(c2566.72,2785) 2600.86,2750.86 cw(c2635,2716.72) R7.1@2635,2765 ; R7.1@2653.19,2776.68 cw(c2666.14,2770.76) 2666.14,2785 ; R7.1@2653.19,2793.32 ccw(c2666.14,2799.24) 2666.14,2785 ; 2682.09,2800.95 cw(c2712.47,2770.58) X3.3@2714.58,2813.48 ; X3.3@2691.53,2810.39 ccw(c2679.83,2822.09) X3.3@2696.38,2822.09 ; X3.3@2701.83,2847.07 ccw(c2670.04,2878.86) 2715,2878.86 ccw(c2759.96,2878.86) X3.3@2728.17,2847.07 ; C11.2@2703.7,2888.42 cw(c2673.58,2867.02) 2709.26,2857.46 cw(c2747.31,2847.27) C11.2@2729.2,2882.24 ; C11.2@2705.86,2885.86 cw(c2683.79,2863.79) 2715,2863.79 cw(c2756.21,2863.79) C11.2@2727.07,2892.93 ; X3.3@2714.09,2803.49 ccw(c2710.97,2740.17) 2666.14,2785 ; X3.3@2714.14,2833 2666.14,2785 ; X3.3 C11.2@2715,2895 ; X3.3@2715,2839.64 cw(c2780.36,2839.64) C11.2@2734.14,2885.86
NetBuzzle1_2: Buzzle1.2 Q1.3 VD3.1 | length 875.7
  Top Layer w10: Buzzle1.2@2500.94,2330.36 cw(c2501.68,2331.1) 2500.63,2331.1 cw(c2501.68,2331.1) Buzzle1.2@2500.94,2331.84 ; 2518.01,2313.29 cw(c2535.82,2331.1) 2510.63,2331.1 cw(c2535.82,2331.1) 2518.01,2348.91 ; 2535.08,2296.22 cw(c2569.96,2331.1) 2520.63,2331.1 cw(c2569.96,2331.1) 2535.08,2365.98 ; 2552.15,2279.15 cw(c2604.1,2331.1) 2530.63,2331.1 cw(c2604.1,2331.1) 2552.15,2383.05 ; Q1.3@2652.27,2496.56 ccw(c2645.69,2489.98) 2645.69,2499.29 ccw(c2645.69,2508.61) Q1.3@2652.27,2502.02 ; Q1.3 2619.29,2499.29 2590,2470 2590,2420.91 Buzzle1.2 2606.3,2225 2723.58,2225 VD3.1 ; 2744.93,2203.65 ccw(c2770,2228.72) VD3.1@2770,2193.27 ; VD3.1@2754.44,2194.15 cw(c2742.81,2182.52) VD3.1@2759.25,2182.52
NetC2_1: C2.1 U1.8 VD2.2 | length 989.9
  Top Layer w10: VD2.2 2928.58,2178.58 C2.1 ; VD2.2@2857.08,2178.58 ccw(c2857.08,2282.92) C2.1@2930.86,2209.14 ; VD2.2@2860.48,2191.3 ccw(c2881.7,2221.41) 2889.29,2185.36 ; VD2.2@2861.88,2170.98 cw(c2880.23,2152.64) 2880.23,2178.58 cw(c2880.23,2204.53) VD2.2@2861.88,2186.18 ; VD2.2@2863.28,2176.65 cw(c2872.35,2170.73) 2870.12,2181.33 ; 2881.22,2178.58 ccw(c2881.22,2258.78) C2.1@2937.93,2202.07 ; 2905.37,2178.58 ccw(c2905.37,2234.63) C2.1 ; C2.1@2961,2183 cw(c2985,2165) 2985,2195 ; C2.1@2961,2207 ccw(c2985,2225) 2985,2195 ; U1.8@3176.57,2438.58 ccw(c3168.3,2446.85) 3180,2446.85 ccw(c3191.69,2446.85) U1.8@3183.42,2438.58 ; U1.8 3180,2450 3160,2470 3120,2470 3107.15,2457.15 3107.15,2357.85 3113,2352 3123,2352 3130.36,2344.64 3130.36,2296.03 3104.33,2270 3035,2270 3015,2250 3015,2225 2985,2195 ; C2.1 2985,2195
NetC4_2: C4.2 U1.1 X1.2 | length 565.4
  Top Layer w10: C4.2@3148.98,2855.86 cw(c3114.84,2821.72) 3163.13,2821.72 cw(c3211.41,2821.72) C4.2@3177.27,2855.86 ; 3157.19,2843.87 ccw(c3202.1,2855.91) X1.2@3182.54,2813.73 ; X1.2@3162.72,2823.22 ccw(c3190.38,2830.63) X1.2@3178.34,2804.66 ; 3163.13,2832.75 ccw(c3196.71,2832.75) X1.2@3178.16,2804.76 ; C4.2@3163.13,2851.37 ccw(c3209.05,2851.37) X1.2@3183.68,2813.09 ; X1.2@3165.75,2780.93 cw(c3131.36,2746.54) U1.1@3180,2746.54 ; U1.1@3175.8,2747.58 ccw(c3164.63,2754.03) 3177.09,2757.37 ; U1.1@3176.57,2748.58 ccw(c3168.3,2756.85) 3180,2756.85 ccw(c3191.69,2756.85) U1.1@3183.42,2748.58 ; 3177.54,2755.72 ccw(c3187.65,2758.43) U1.1@3182.42,2749.35 ; U1.1@3180,2710 3180,2798.92 X1.2 3163.13,2815.79 C4.2 ccw(c3221.4,2870) X1.2@3189.21,2821.43 ; U1.1@3180,2751.74 cw(c3221.27,2751.74) X1.2@3192.09,2780.93 ; 3182.44,2760.86 ccw(c3199.35,2756.33) U1.1@3184.19,2747.58
NetC10_2: C10.2 IC1.4 R4.1 R5.2 | length 1464.1
  Bottom Layer w10: R5.2@1760.86,2670.86 cw(c1726.72,2636.72) 1775,2636.72 cw(c1823.28,2636.72) R5.2@1789.14,2670.86 ; R5.2 1775,2475 1942.4,2307.6 IC1.4 2004.88,2280.12 2040,2245 2135,2245 2195,2305 ; IC1.4@1987.68,2304.17 ccw(c1979.41,2295.91) 1979.41,2307.6 ccw(c1979.41,2319.29) IC1.4@1987.68,2311.02 ; IC1.4@2001.46,2304.17 cw(c1993.19,2295.91) 2004.88,2295.91 cw(c2016.57,2295.91) IC1.4@2008.31,2304.17 ; C10.2@2184.85,2322.77 cw(c2174.38,2305) 2195,2305 ; C10.2@2187.31,2358.46 ccw(c2182.5,2370) 2195,2370 ; 2195.44,2370.44 ccw(c2210.89,2354.99) C10.2 ; C10.2@2202.27,2346.86 cw(c2218.38,2362.06) 2202.72,2377.72 ; C10.2@2202.69,2358.46 cw(c2207.5,2370) 2195,2370 ; C10.2@2205.15,2322.77 ccw(c2215.62,2305) 2195,2305 ; C10.2@2209.55,2353.73 cw(c2225.87,2369.13) 2210,2385 ; R4.1@2420,2430 cw(c2371.72,2430) 2405.86,2395.86 cw(c2440,2361.72) R4.1@2440,2410 ; R4.1 2395,2385 2210,2385 ; 2195,2305 C10.2 ; C10.2 2195,2370 ; 2195,2370 2210,2385
NetF1_1: F1.1 VD1.1 | length 129.1
  Top Layer w15: VD1.1@1947.99,2844.17 cw(c1931.34,2827.52) 1954.88,2827.52 ; F1.1@1948.42,2790.83 ccw(c1932.81,2806.44) 1954.88,2806.44 ; 1954.88,2803.38 ccw(c1972.63,2803.38) F1.1@1960.08,2790.83 ; 1954.88,2832.65 cw(c1971.16,2832.65) VD1.1@1959.65,2844.17 ; VD1.1@1954.88,2850 1954.88,2788.62 F1.1
NetF1_2: F1.2 USB1.1 | length 264.3
  Top Layer w16: USB1.1 2011.01,2606.01 2024,2619 2024,2777.5 F1.2@2024.5,2778 ; 2024,2758.45 cw(c2053.79,2758.45) F1.2@2032.73,2779.52
NetIC1_1: IC1.1 LED2.2 | length 605
  Top Layer w10: LED2.2 1897.84,2782.16 v1(1985,2695) ; LED2.2@1864.84,2773.32 cw(c1886.18,2751.98) 1886.18,2782.16 cw(c1886.18,2812.34) LED2.2@1864.84,2791 ; v1(2045,2635) 2045,2595 2115.12,2524.88 v1(2115.12,2399.88)
  Bottom Layer w10: v1(1985,2695) v1(2045,2635) ; IC1.1@2111.69,2385.83 ccw(c2103.43,2394.09) 2115.12,2394.09 ccw(c2126.81,2394.09) IC1.1@2118.54,2385.83 ; v1@2115,2400 v1(2115.12,2399.88) IC1.1
NetIC1_5: IC1.5 LED1.2 | length 629.9
  Bottom Layer w10: v1(1850,2860.26) 1850,2445 1950,2345 IC1.5 ; IC1.5@1987.68,2341.58 ccw(c1979.41,2333.31) 1979.41,2345 ccw(c1979.41,2356.69) IC1.5@1987.68,2348.42
NetIC1_6: IC1.6 R9.2 | length 169.9
  Bottom Layer w10: R9.2@2000.86,2445.86 cw(c1966.72,2411.72) 2015,2411.72 cw(c2063.28,2411.72) R9.2@2029.14,2445.86 ; 2015,2402.93 ccw(c2039.19,2402.93) IC1.6@2022.09,2385.83 ; R9.2 2015,2392.52 ccw(c2020.43,2392.52) IC1.6@2019.49,2387.17
NetLED1_1: LED1.1 LED2.1 R5.1 | length 166.9
  Top Layer w15: LED2.1@1771.43,2789.23 ccw(c1750.72,2809.94) 1780,2809.94 ; LED1.1@1772.93,2853.18 cw(c1755.86,2836.11) 1780,2836.11 cw(c1804.15,2836.11) LED1.1@1787.08,2853.18 ; LED2.1 1780,2783.67 LED1.1 ; 1780,2802.67 ccw(c1799.01,2802.67) LED2.1@1785.57,2789.23 ; LED2.1@1782.29,2783.99 ccw(c1767.95,2790.34) LED2.1@1782.58,2795.99
  other v1: 1780,2785
NetQ1_1: Q1.1 R15.2 | length 318.3
  Top Layer w10: Q1.1@2614.87,2396.45 cw(c2608.28,2389.86) 2617.6,2389.86 cw(c2626.91,2389.86) Q1.1@2620.33,2396.45 ; Q1.1 2617.6,2377.4 2617.69,2377.31 2762.31,2377.31 R15.2 ; 2703.16,2377.31 ccw(c2703.16,2451.84) R15.2@2755.86,2399.14 ; 2727.3,2377.31 ccw(c2727.3,2427.7) R15.2@2762.93,2392.07 ; 2740.27,2377.31 cw(c2740.27,2355.27) R15.2@2755.86,2370.86
NetU1_2: U1.2 X1.1 | length 251.2
  Top Layer w10: X1.1 3115,2800 3130,2785 U1.2@3130,2710 ; X1.1@3062.16,2786.83 cw(c3093.95,2755.04) 3093.95,2800 cw(c3093.95,2844.96) X1.1@3062.16,2813.17 ; U1.2@3126.57,2748.58 ccw(c3118.3,2756.85) 3130,2756.85 ccw(c3141.69,2756.85) U1.2@3133.42,2748.58
NRST: *1.7 C15.2 R14.1 | length 631.4
  Top Layer w10: v1(2455.16,2734.84) *1.7
  Bottom Layer w10: v1@2455,2735 2513,2793 2632,2793 C15.2 ; C15.2@2665,2740 ccw(c2616.72,2740) 2650.86,2774.14 ccw(c2685,2808.28) C15.2@2685,2760
  Bottom Layer w15: C15.2@2672.63,2727.63 cw(c2639.48,2694.48) 2686.35,2694.48 ; R14.1@2673.98,2662.37 ccw(c2644.11,2692.25) 2686.35,2692.25 ccw(c2728.6,2692.25) R14.1@2698.73,2662.37 ; C15.2 2685,2735 2686.35,2733.65 R14.1 ; 2686.35,2701.02 cw(c2723.98,2701.02) C15.2@2697.37,2727.63
OLED_DC_PIN: *1.32 外接排线1.11 | length 1055.3
  Top Layer w10: *1.32 2275.47,2695.47 v1(2300,2720)
  Bottom Layer w10: v1(2300,2720) 2555,2975 2885,2975 2925,3015 ; 外接排线1.11@2908.56,3046.76 cw(c2886.1,3015) 2925,3015 ; 外接排线1.11@2914.34,3054.93 cw(c2899.77,3034.32) 2925,3034.32 cw(c2950.23,3034.32) 外接排线1.11@2935.66,3054.93 ; 外接排线1.11 2925,3015 ; 外接排线1.11@2941.44,3046.76 ccw(c2963.9,3015) 2925,3015
OLED_RST_PIN: *1.33 外接排线1.12 | length 1315.1
  Top Layer w10: *1.33 2290.79,2675.79 v1(2300,2685)
  Bottom Layer w10: v1(2300,2685) 2560,2945 2925,2945 3025,3045 外接排线1.12 ; 2958.73,2978.73 ccw(c2867.46,3070) 外接排线1.12@2996.54,3070 ; 2975.8,2995.8 ccw(c2901.6,3070) 外接排线1.12@3006.54,3070 ; 2992.87,3012.87 ccw(c2935.75,3070) 外接排线1.12@3016.54,3070 ; 3009.94,3029.94 ccw(c2969.89,3070) 外接排线1.12@3026.54,3070
OLED_SCK_PIN: *1.15 外接排线1.10 | length 690
  Top Layer w10: *1.15 2413.9,2953.9 2424,2964 2779,2964 2825,3010 ; 外接排线1.10@2806.99,3047.95 cw(c2776,3010) 2825,3010 ; 外接排线1.10@2813.32,3055.7 cw(c2793.22,3031.08) 2825,3031.08 cw(c2856.78,3031.08) 外接排线1.10@2836.68,3055.7 ; 外接排线1.10@2825,3060 2825,3010 ; 外接排线1.10@2843.01,3047.95 ccw(c2874,3010) 2825,3010
OLED_SDA_PIN: *1.17 外接排线1.9 | length 648.7
  Top Layer w10: *1.17@2375.31,2892.2 2375.31,2950.31 2407,2982 2702,2982 2725,3005 ; 外接排线1.9@2705.7,3049.08 cw(c2665.03,3005) 2725,3005 ; 外接排线1.9@2712.48,3056.43 cw(c2686.1,3027.84) 2725,3027.84 cw(c2763.9,3027.84) 外接排线1.9@2737.52,3056.43 ; 外接排线1.9@2725,3060 2725,3005 ; 外接排线1.9@2744.3,3049.08 ccw(c2784.97,3005) 2725,3005
PA0: *1.10 C1.2 Switch1.2 U1.3 | length 2624.8
  Top Layer w10: v1(1845,3045) 1845,3055.57 Switch1.2 ; v1(1945,3120) v1(2005,3120) ; v1(2450,2805) 2461.1,2793.9 *1.10 ; U1.3 3080,2755 v1(3095,2770) ccw(c3119.53,2745.47) U1.3@3084.84,2745.2
  Bottom Layer w10: C1.2@1834.85,3062.23 ccw(c1824.38,3080) 1845,3080 ; v1(1845,3045) 1845,3080 ; C1.2@1855.15,3062.23 cw(c1865.62,3080) 1845,3080 ; v1(1945,3120) 1885,3120 1845,3080 ; v1(2005,3120) 3105,3120 3140,3085 3140,2900 3095,2855 3010,2855 ; v1(2450,2805) 2500,2855 3010,2855 ; v1(3095,2770) 3010,2855
PA2: *1.12 C3.2 Switch2.2 | length 952.9
  Top Layer w10: Switch2.2 1911.57,2321.57 v1(2095,2505) ; Switch2.2@1878.07,2318.15 cw(c1886.34,2309.88) 1886.34,2321.57 cw(c1886.34,2333.27) Switch2.2@1878.07,2325 ; v1(2415,2710) 2415,2795.46 2452.81,2833.27 *1.12
  Top Layer w20: v1(1860,2300) 1860,2320.71 Switch2.2
  Bottom Layer w10: v1(2095,2505) 2122.73,2532.73 2222.27,2532.73 2399.54,2710 v1(2415,2710)
PA3: *1.13 C5.2 Switch3.2 | length 982.7
  Top Layer w10: *1.13 2600.42,2891.42 2649,2940 2830,2940 2870,2980 v1(3000,2980)
  Top Layer w20: Switch3.2 3095,2934.29 v1(3095,2955)
  Bottom Layer w10: 3021.11,2980 cw(c3021.11,2894.51) C5.2@3087.26,2948.67 ; 3042.22,2980 cw(c3042.22,2911.79) v1(3095,2955) 3070,2980 v1(3000,2980) cw(c3000,2877.23) C5.2@3079.52,2942.33 ; 3063.33,2980 cw(c3063.33,2929.08) C5.2@3102.74,2961.33
PA4: *1.14 C6.2 Switch4.2 | length 1669.6
  Top Layer w10: *1.14 2433.58,2939.58 2440,2946 2569,2946 v1(2595,2920) ; 3039.65,2928.93 ccw(c3025,2914.28) v1(3025,2935) 3033.58,2935 3060.58,2908 3103.51,2908 3120,2891.51 v1(3120,2825)
  Top Layer w20: Switch4.2 3095,2190.43 v1(3095,2215)
  Bottom Layer w10: v1(2595,2920) 2960,2920 2975,2935 v1(3025,2935) ; v1(3095,2215) 3140,2260 3140,2315 3200,2375 3200,2790 3165,2825 v1(3120,2825) ; C6.2@3095,2235 ccw(c3095,2283.28) 3129.14,2249.14 ccw(c3163.28,2215) C6.2@3115,2215
PA6: *1.16
PA8: *1.29 外接排线1.3 | length 598.7
  Top Layer w10: *1.29 2229.53,2754.53 2244,2769 v1(2244,2794)
  Bottom Layer w10: 外接排线1.3@2104.87,3049.87 cw(c2056.28,3001.28) 2125,3001.28 cw(c2193.72,3001.28) 外接排线1.3@2145.13,3049.87 ; 外接排线1.3@2111.94,3056.94 cw(c2080.42,3025.42) 2125,3025.42 cw(c2169.58,3025.42) 外接排线1.3@2138.06,3056.94 ; 外接排线1.3 2125,2913 v1(2244,2794)
PA9: *1.30 外接排线1.4 | length 599.1
  Top Layer w10: *1.30 2241.84,2734.84 2262,2755 v1(2262,2775)
  Bottom Layer w10: 外接排线1.4@2204.87,3049.87 cw(c2156.28,3001.28) 2225,3001.28 cw(c2293.72,3001.28) 外接排线1.4@2245.13,3049.87 ; 外接排线1.4@2211.94,3056.94 cw(c2180.42,3025.42) 2225,3025.42 cw(c2269.58,3025.42) 外接排线1.4@2238.06,3056.94 ; 外接排线1.4 2225,2895 2262,2858 v1(2262,2775)
PA10: *1.31 外接排线1.5 | length 614
  Top Layer w10: *1.31 2249.7,2715.16 2280,2745.46 v1(2280,2760)
  Bottom Layer w10: v1(2280,2760) 2280,3025 ; 外接排线1.5@2296.58,3068.41 cw(c2239.77,3065.24) 2280,3025 ; 外接排线1.5@2306.56,3068.97 cw(c2269.71,3066.91) 2295.81,3040.81 cw(c2321.91,3014.71) 外接排线1.5@2323.97,3051.56 ; 外接排线1.5@2323.41,3041.58 ccw(c2320.24,2984.77) 2280,3025 ; 外接排线1.5 2280,3025
PB2: *1.20 R10.2 | length 452.6
  Top Layer w10: v1(2315,2845) 2315.47,2845.47 *1.20
  Bottom Layer w10: R10.2@2192.32,2736.82 ccw(c2242.47,2783.55) 2242.47,2715 ; R10.2@2199.63,2743.63 ccw(c2265.45,2804.97) 2265.45,2715 ; 2219.48,2715 cw(c2219.48,2762.13) R10.2 2200,2715 2265.46,2715 ; v1(2315,2845) 2315,2764.54 2265.46,2715
PB5: *1.41
PB6: *1.42 R2.2 U1.6 | length 1152
  Top Layer w10: *1.42 v1(2335.16,2614.84) v1@2335.16,2615 ; v1(2479.77,2509.77) v1@2519.89,2549.89 ; v1@2598,2553 v1(2665,2553) ; R2.2 v1(2907.5,2525) 2917.5,2535 3040,2535 3080,2495 U1.6@3080,2400 ; R2.2@2857.5,2495 ccw(c2857.5,2543.28) 2891.64,2509.14 ccw(c2925.78,2475) R2.2@2877.5,2475 ; U1.6@3076.57,2438.58 ccw(c3068.3,2446.85) 3080,2446.85 ccw(c3091.69,2446.85) U1.6@3083.42,2438.58
  Bottom Layer w10: v1(2335.16,2614.84) 2440.23,2509.77 v1(2479.77,2509.77) ; v1(2522,2553) v1(2597,2553) ; v1(2665,2553) 2882,2553 2907.5,2527.5 v1(2907.5,2525)
PB7: *1.43 R1.2 U1.5 | length 1165
  Top Layer w10: *1.43 2354.84,2604.84 2365,2615 v1(2400,2615) ; R1.2@2937.31,2493.46 ccw(c2932.5,2505) v1(2945,2505) ; R1.2@2945,2455 cw(c2945,2382.58) 2996.21,2433.79 ; R1.2@2945,2465 cw(c2945,2416.72) 2979.14,2450.86 ; R1.2@2952.69,2493.46 cw(c2957.5,2505) v1(2945,2505) ; R1.2@2961.71,2468.29 ccw(c3030,2536.57) U1.5@3030,2440 ; R1.2@2965,2475 ccw(c2989.15,2475) 2972.07,2457.93 ; 2978.78,2451.22 ccw(c3030,2502.43) U1.5@3030,2430 ; 2995.85,2434.15 ccw(c3030,2468.29) U1.5@3030,2420 ; 3012.92,2417.07 ccw(c3030,2434.15) U1.5@3030,2410 ; U1.5@3030,2400 2955,2475 R1.2 v1(2945,2505)
  Bottom Layer w10: v1(2400,2615) 2420,2615 2530,2505 v1(2945,2505)
PB8: *1.45
PB9: *1.46
PB12: *1.25 JP3.1 | length 2116.7
  Top Layer w10: 2117.55,2895.3 cw(c2055.51,2833.27) *1.25@2143.24,2833.27 ; 2134.62,2878.23 cw(c2089.66,2833.27) *1.25@2153.24,2833.27 ; 2151.69,2861.16 cw(c2123.8,2833.27) *1.25@2163.24,2833.27 ; 2168.76,2844.09 cw(c2157.94,2833.27) *1.25@2173.24,2833.27 ; *1.25 2100.85,2912 2048,2912 1960,3000 1842.84,3000 1820,3022.84 1820,3095 1860,3135 1860,3225 1895,3260 3005,3260 3030,3235 ; JP3.1@3017.8,3215.72 ccw(c3008.66,3235) 3030,3235 ; JP3.1@3030,3180 JP3.1 3030,3235 ; JP3.1@3042.2,3215.72 cw(c3051.34,3235) 3030,3235
PB13: *1.26 JP4.1 | length 745.8
  Top Layer w10: v1(1975,2905) 1995,2885 2075,2885 2100,2860 2100,2830 2116.42,2813.58 *1.26
  Bottom Layer w10: JP4.1@1920,3161.54 cw(c1920,3092.82) 1968.59,3141.41 cw(c2017.18,3190) JP4.1@1948.46,3190 ; JP4.1@1920,3171.54 cw(c1920,3126.96) 1951.52,3158.48 cw(c1983.04,3190) JP4.1@1938.46,3190 ; JP4.1 1975,3135 v1(1975,2905)
PB14: *1.27
PB15: *1.28
PC13: *1.2
PC14: *1.3 C7.2 X2.2 | length 542.6
  Top Layer w10: *1.3 2563.9,2656.1 2575,2645 2575,2580 2583,2572 2647,2572 v1(2647.5,2572.5) ; C7.2 v1(2895,2675) X2.2
  Bottom Layer w10: v1(2647.5,2572.5) 2832.5,2572.5 2895,2635 v1(2895,2675)
PC15: *1.4 C8.2 X2.1 | length 601.2
  Top Layer w10: *1.4 2579.21,2675.79 v1(2625,2630) ; v1(2890,2815) ccw(c2877.93,2827.07) X2.1@2895,2827.07 ; C8.2 X2.1@2895,2830
  Bottom Layer w10: v1(2625,2630) 2647.5,2607.5 2827.5,2607.5 2850,2630 2850,2775 v1(2890,2815)
TCLK: *1.37 R16.2 TCLK1.1 | length 1706.7
  Top Layer w10: v1(2236.73,2503.27) *1.37 ; v1(2980,2585) 2980,2620 v1(3005,2645)
  Bottom Layer w10: v1(2236.73,2503.27) 2253,2487 2957,2487 2980,2510 v1(2980,2585) ; v1(3005,2645) 3020,2660 3045,2660 ; R16.2@3048.36,2693.91 cw(c3026,2679) 3045,2660 ; 3053.63,2668.63 ccw(c3036.35,2685.9) R16.2@3056.68,2699.45 ; 3062.25,2677.25 ccw(c3046.7,2692.8) R16.2 ; R16.2@3065,2725 ccw(c3065,2773.28) 3099.14,2739.14 ccw(c3133.28,2705) R16.2@3085,2705 ; R16.2@3079.15,2719.15 cw(c3140.44,2657.86) TCLK1.1@3152.67,2743.67 ; 3093.3,2733.3 cw(c3143.97,2682.63) TCLK1.1@3154.08,2753.57 ; 3107.44,2747.44 cw(c3147.5,2707.39) TCLK1.1@3155.49,2763.47 ; 3121.59,2761.59 cw(c3151.03,2732.15) TCLK1.1@3156.91,2773.37 ; TCLK1.1@3129.5,2752.81 ccw(c3120,2750.13) 3120,2760 ; TCLK1.1@3129.5,2767.19 cw(c3120,2769.87) 3120,2760 ; TCLK1.1@3151.26,2733.77 ccw(c3136.91,2633.1) R16.2 ; TCLK1.1 3120,2760 ; 3045,2660 3065,2680 R16.2 ; R16.2 3120,2760
TD0/PB3: *1.39
TDI/PA15: *1.38
TMS: *1.34 R13.1 TMS1.1 | length 1404.5
  Top Layer w10: *1.34 2117.81,2656.1 2110,2648.29 2110,2620.91 2210.91,2520 2211,2520 2211,2479 v1(2220,2470) ; v1(3000,2470) 3045,2480 v1(3050,2485) ; v1(3050,2485) cw(c3039.07,2491.96) 3041.88,2479.31 ccw(c3039.07,2491.96) v1(3050,2485)
  Bottom Layer w10: v1(2220,2470) 2221,2469 2999,2469 v1(3000,2470) ; v1(3050,2485) R13.1@3065,2485 ; R13.1 3121.67,2490 ; R13.1@3079.14,2475.86 cw(c3113.28,2441.72) 3113.28,2490 cw(c3113.28,2538.28) R13.1@3079.14,2504.14 ; TMS1.1@3129.26,2517.07 cw(c3101.39,2510.28) 3121.67,2490 ; TMS1.1@3148.73,2497.59 ccw(c3141.95,2469.72) 3121.67,2490 ; TMS1.1 3121.67,2490
TRST/PB4: *1.40
VBAT: *1.1 R3.2 | length 259.4
  Top Layer w10: *1.1 2540,2588.15 R3.2 ; R3.2@2525.86,2459.14 ccw(c2491.72,2493.28) 2540,2493.28 ccw(c2588.28,2493.28) R3.2@2554.14,2459.14
VDDA: *1.9 R8.2 | length 383
  Top Layer w10: v1(2457.83,2773.43) *1.9@2520.63,2773.43
  Bottom Layer w10: v1(2457.83,2773.43) 2499.41,2815 R8.2 ; R8.2@2670.86,2800.86 ccw(c2636.72,2766.72) 2636.72,2815 ccw(c2636.72,2863.28) R8.2@2670.86,2829.14
VUSB: R4.2 VD1.2 | length 727.5
  Top Layer w10: VD1.2@2065.12,2845 VD1.2@2065.12,2861.08
  Top Layer w20: VD1.2@2059.99,2845.94 cw(c2037.03,2822.98) 2069.5,2822.98 ; VD1.2 2065.12,2845 2069.5,2840.62 2069.5,2615.5 2165,2520 2165,2461 v1(2193,2433)
  Bottom Layer w10: v1(2193,2433) v1@2196,2433
  Bottom Layer w20: v1@2196,2430 R4.2 ; R4.2@2339.39,2419.39 ccw(c2313.79,2393.79) 2313.79,2430 ccw(c2313.79,2466.21) R4.2@2339.39,2440.61
pads on no net: Buzzle1.3 Switch1. Switch2. Switch3. Switch4. U1.7 USB1.4
copper on no net:
  other v2: 1790,2220 3165,2224.21 1790,2286.93 3165,2291.14 3165,2968.07 1789,2968.86 3165,3035 1789,3035.79
  other v3: 2512.01,2260.24 2637.99,2260.24

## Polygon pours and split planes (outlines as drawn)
GND on Top Layer "Bottom Layer-No Net" (solid, pour order 2): 1870,3140 1870,2125 3080,2125 3080,3140
GND on Bottom Layer "Bottom Layer-No Net" (solid, pour order 4): 1870,3140 1870,2125 3080,2125 3080,3140

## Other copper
Top Layer:
  rectangle net +: 2060,2270 2245,2310
Bottom Layer:
  rectangle net +: 2060,2270 2140,2320

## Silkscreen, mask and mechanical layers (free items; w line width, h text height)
Mechanical 1:
  lines w3.94: 2044.76,2034.04 cw(c2044.76,2073.41) 2044.76,2112.78 2910.91,2112.78 cw(c2910.91,2073.41) 2910.91,2034.04 2044.76,2034.04 ; 2046.65,3147.39 cw(c2046.65,3186.76) 2046.65,3226.13 2912.79,3226.13 cw(c2912.79,3186.76) 2912.79,3147.39 2046.65,3147.39
  lines w10: 1740,2165 ccw(c1749.11,2163.73) 1747.84,2154.61 cw(c1740,2075) 1820,2075 ccw(c1930,2075) 1930,1965 3030,1965 ccw(c3030,2075) 3140,2075 cw(c3210,2075) 3203.14,2144.66 ccw(c3201.4,2153.26) 3210,2155 3210,3085 ccw(c3199.75,3085.2) 3199.94,3095.45 cw(c3209.17,3189.17) 3115,3188.35 ccw(c3009.17,3189.17) 3010,3295 1935,3295 ccw(c1935,3190) 1830,3190 cw(c1740,3190) 1748.82,3100.43 ccw(c1749.63,3090.81) 1740,3090 1740,2165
